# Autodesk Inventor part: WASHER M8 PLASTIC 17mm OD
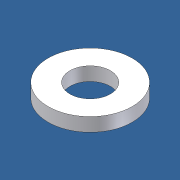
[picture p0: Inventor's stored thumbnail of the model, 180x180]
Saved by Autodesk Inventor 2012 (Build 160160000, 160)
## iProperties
Created: 2007-06
Part Number: WASHER M8 PLASTIC 17mm OD
Material: UHMW, White
Document SubType Name: Modeling
Designer: Andy Moles
Density: 0.94 g/cm^3
Mass: 0.450229 g
Surface Area: 5.66052 cm^2
Volume: 0.478967 cm^3
Author: Andy Moles
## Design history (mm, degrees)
sketch "Sketch1"
  geometry: C1 r 4.1 at (0, 0); C2 r 8.5 at (0, 0); 1 further point
  constraints: 2 centre point, 2 coincident
  dimensions: "d0" = 8.2 diameter of C1; "d1" = 17 diameter of C2
extrude "Extrusion1" new body sketch "Sketch1" distance "d2" = 2.75; taper "d3" = 0 deg
body "Solid1"
